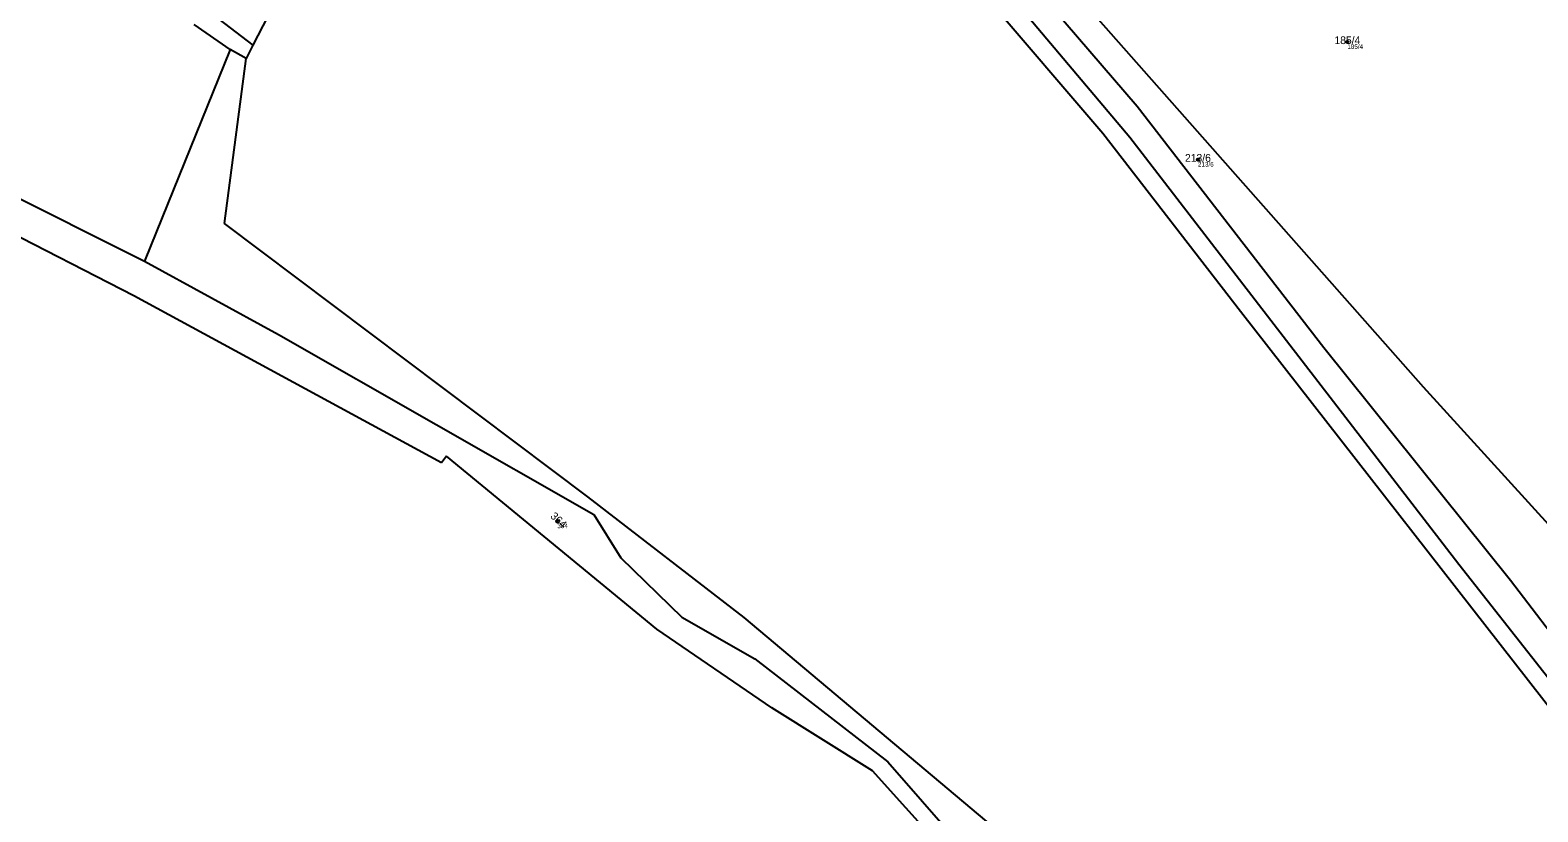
# Model space of a CAD drawing. Extents: x -867966 to -864255, y -1043242 to -1041327.
# Drawn here: x -865661.4 to -865330.3, y -1042193.8 to -1042022 of the extents above; entities that cross this region are included whole.
import ezdxf

# ---------------------------------------------------------------- set-up
doc = ezdxf.new("R2010")
doc.units = 0
for name, color, linetype in [('Definiční body', 7, 'Continuous'), ('Hranice parcel', 7, 'Continuous'), ('Parcelní čísla', 7, 'Continuous')]:
    doc.layers.add(name, color=color, linetype=linetype)

msp = doc.modelspace()

# ---------------------------------------------------------------- linework, layer by layer
at = {"layer": 'Definiční body'}
for centre in [(-865372.14, -1042024.65), (-865404.95, -1042050.51), (-865545.62, -1042129.97)]:
    msp.add_circle(centre, 0.25, dxfattribs=at)
at = {"layer": 'Hranice parcel'}
for p, q in [((-865464.77, -1041984.64), (-865418.27, -1042038.75)), ((-865457.75, -1041984.58), (-865355.47, -1042100.41)), ((-865467.47, -1041989.05), (-865419.94, -1042045.55)), ((-865425.81, -1042044.73), (-865471.2, -1041991.73)), ((-865598.9, -1041998.76), (-865612.46, -1042025.32)), ((-865622.46, -1042017.71), (-865612.46, -1042025.32)), ((-865617.45, -1042026.24), (-865625.34, -1042020.75)), ((-865617.45, -1042026.24), (-865636.25, -1042072.8)), ((-865613.98, -1042028.24), (-865617.45, -1042026.24)), ((-865612.46, -1042025.32), (-865613.98, -1042028.24)), ((-865618.7, -1042064.52), (-865613.98, -1042028.24)), ((-865704.5, -1042038.59), (-865636.25, -1042072.8)), ((-865418.27, -1042038.75), (-865377.34, -1042091.75)), ((-865395.62, -1042083.87), (-865425.81, -1042044.73)), ((-865419.94, -1042045.55), (-865347.67, -1042139.36)), ((-865638.61, -1042080.38), (-865704.23, -1042046.72)), ((-865538.95, -1042124.56), (-865618.7, -1042064.52)), ((-865636.25, -1042072.8), (-865606.86, -1042088.87)), ((-865571.07, -1042117.09), (-865638.61, -1042080.38)), ((-865316.93, -1042184.85), (-865395.62, -1042083.87)), ((-865606.86, -1042088.87), (-865537.63, -1042128.46)), ((-865377.34, -1042091.75), (-865336.33, -1042142.85)), ((-865355.47, -1042100.41), (-865299.13, -1042162.49)), ((-865569.94, -1042115.6), (-865571.07, -1042117.09)), ((-865523.77, -1042153.65), (-865569.94, -1042115.6)), ((-865504.6, -1042151.12), (-865538.95, -1042124.56)), ((-865537.63, -1042128.46), (-865531.69, -1042138)), ((-865531.69, -1042138), (-865518.3, -1042150.98)), ((-865347.67, -1042139.36), (-865309.98, -1042187.35)), ((-865336.33, -1042142.85), (-865310.45, -1042176.82)), ((-865518.3, -1042150.98), (-865502.23, -1042160.2)), ((-865443.94, -1042202.1), (-865504.6, -1042151.12)), ((-865498.53, -1042170.96), (-865523.77, -1042153.65)), ((-865502.23, -1042160.2), (-865473.02, -1042182.79)), ((-865476.39, -1042184.77), (-865498.53, -1042170.96)), ((-865461.75, -1042201.03), (-865476.39, -1042184.77)), ((-865473.02, -1042182.79), (-865457.86, -1042200.24))]:
    msp.add_line(p, q, dxfattribs=at)

# ---------------------------------------------------------------- texts
at = {"layer": 'Definiční body'}
for s, p in [('185/4', (-865372.14, -1042026.14)), ('213/6', (-865404.95, -1042052)), ('364', (-865545.62, -1042131.46))]:
    msp.add_text(s, height=1, dxfattribs=at).set_placement(p)
at = {"layer": 'Parcelní čísla'}
for s, p in [('185/4', (-865374.98, -1042025.08)), ('213/6', (-865407.79, -1042050.94))]:
    msp.add_text(s, height=1.7, dxfattribs=at).set_placement(p)
msp.add_text('364', height=1.7, rotation=317, dxfattribs=at).set_placement((-865547.29, -1042128.99))

doc.saveas('drawing.dxf')
